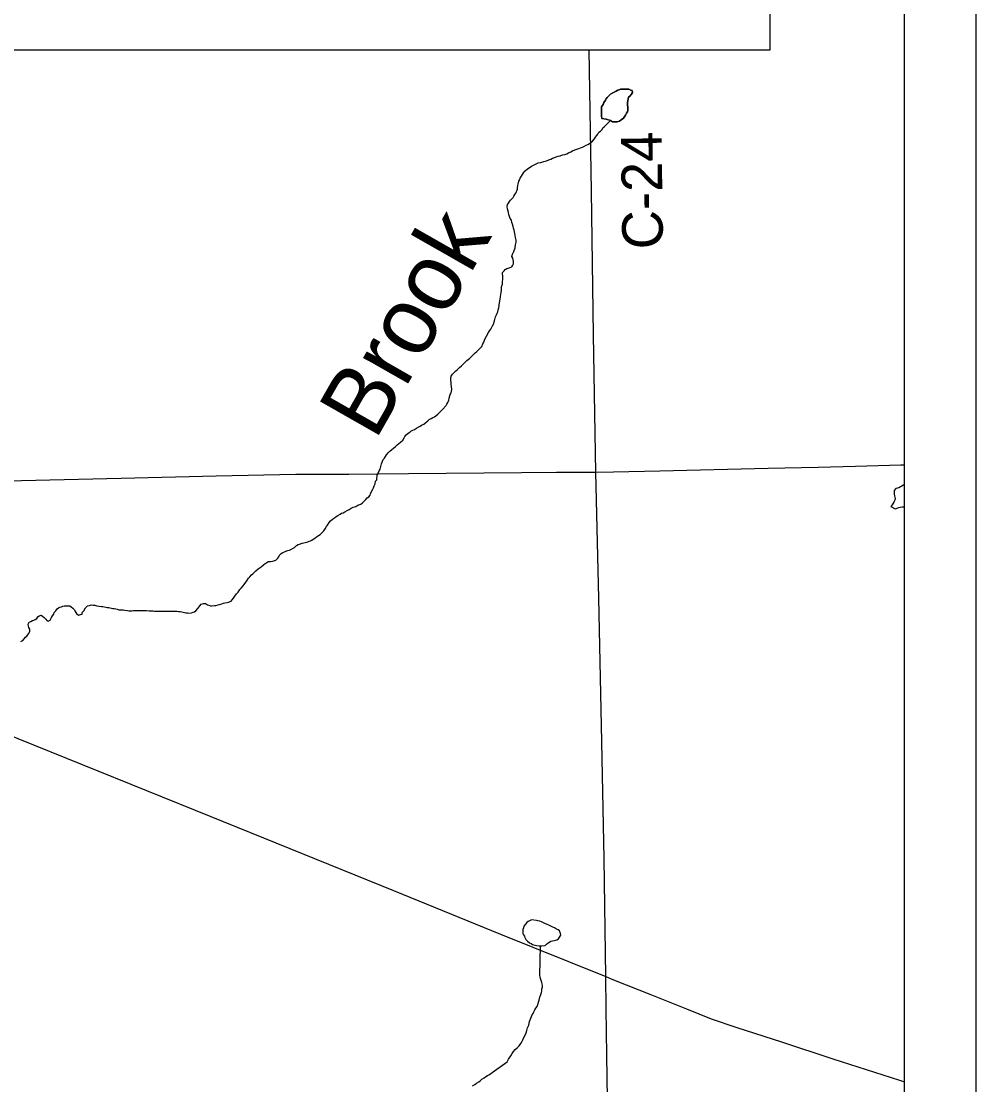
# Model space of a CAD drawing. Extents: x 0 to 34, y 0 to 22.
# Drawn here: x 7.926 to 9.262, y 16.207 to 17.696 of the extents above; entities that cross this region are included whole.
import ezdxf

# ---------------------------------------------------------------- set-up
doc = ezdxf.new("R2010")
doc.units = 0
for name, color, linetype in [('GM_X_County', 7, 'Continuous'), ('GM_X_County_Road', 7, 'Continuous'), ('GM_X_County_Road_Text', 7, 'Continuous'), ('GM_X_Minor_Lake', 7, 'Continuous'), ('GM_X_Minor_River', 7, 'Continuous'), ('GM_X_Minor_River_Text', 7, 'Continuous'), ('GM_X_Township', 7, 'Continuous'), ('GM_X_Township_Road', 7, 'Continuous'), ('GM_X_US_Route', 7, 'Continuous'), ('SH_Border', 7, 'Continuous'), ('SH_Data', 7, 'Continuous')]:
    doc.layers.add(name, color=color, linetype=linetype)

msp = doc.modelspace()

# ---------------------------------------------------------------- linework, layer by layer
at = {"layer": 'GM_X_County'}
msp.add_lwpolyline([(9.1622, 14.342), (9.1622, 21.1385), (2.3622, 21.1385), (2.3622, 14.3385), (9.0003, 14.3385)], dxfattribs=at)
at = {"layer": 'GM_X_County_Road'}
for points in [[(8.7438, 16.3585), (8.7415, 16.5238), (8.7381, 16.7101), (8.7342, 16.8882), (8.73, 17.0642), (8.7267, 17.2567), (8.7237, 17.4579), (8.7206, 17.6552)], [(8.7838, 14.3385), (8.7824, 14.3532), (8.7805, 14.4411), (8.7792, 14.5521), (8.7772, 14.6534), (8.7751, 14.7509), (8.773, 14.8406), (8.7698, 14.9457), (8.7683, 15.0013), (8.7648, 15.1439), (8.7597, 15.3395), (8.7581, 15.4244), (8.756, 15.5234), (8.7553, 15.5899), (8.7512, 15.8644), (8.748, 16.0625), (8.7455, 16.2486), (8.7445, 16.3137), (8.7438, 16.3585)]]:
    msp.add_lwpolyline(points, dxfattribs=at)
at = {"layer": 'GM_X_Minor_Lake'}
for points in [[(8.7789, 17.5993), (8.7762, 17.6004), (8.7739, 17.6007), (8.7712, 17.6007), (8.7694, 17.6007), (8.7671, 17.6007), (8.7644, 17.6003), (8.7625, 17.5995), (8.7606, 17.5991), (8.7584, 17.5976), (8.7557, 17.5964), (8.7538, 17.5953), (8.7504, 17.5933), (8.7482, 17.5911), (8.7459, 17.5888), (8.7444, 17.5868), (8.7433, 17.5849), (8.7414, 17.5819), (8.7403, 17.5792), (8.738, 17.5758), (8.7381, 17.5724), (8.7377, 17.5697), (8.7377, 17.567), (8.7381, 17.5632), (8.7382, 17.5594), (8.7445, 17.5584)], [(8.7445, 17.5584), (8.7382, 17.5594), (8.7381, 17.5632), (8.7377, 17.567), (8.7377, 17.5697), (8.7381, 17.5724), (8.738, 17.5758), (8.7403, 17.5792), (8.7414, 17.5819), (8.7433, 17.5849), (8.7444, 17.5868), (8.7459, 17.5888), (8.7482, 17.5911), (8.7504, 17.5933), (8.7538, 17.5953), (8.7557, 17.5964), (8.7584, 17.5976), (8.7606, 17.5991), (8.7625, 17.5995), (8.7644, 17.6003), (8.7671, 17.6007), (8.7694, 17.6007), (8.7712, 17.6007), (8.7739, 17.6007), (8.7762, 17.6004), (8.7789, 17.5993), (8.7808, 17.5985), (8.7812, 17.5959), (8.7797, 17.5936), (8.7774, 17.5905), (8.7755, 17.5894), (8.7751, 17.5871), (8.7748, 17.5844), (8.7744, 17.5817), (8.7744, 17.5798), (8.7745, 17.5779), (8.7749, 17.576), (8.7749, 17.5741), (8.7749, 17.5711), (8.7741, 17.5688), (8.773, 17.5669), (8.7715, 17.5642), (8.7685, 17.56), (8.7655, 17.5574), (8.7629, 17.5558), (8.7598, 17.5547), (8.7579, 17.5546), (8.7553, 17.5546), (8.7534, 17.555), (8.7507, 17.5565), (8.7445, 17.5584)], [(8.7445, 17.5584), (8.7507, 17.5565), (8.7534, 17.555), (8.7553, 17.5546), (8.7579, 17.5546), (8.7598, 17.5547), (8.7629, 17.5558), (8.7655, 17.5574), (8.7685, 17.56), (8.7715, 17.5642), (8.773, 17.5669), (8.7741, 17.5688), (8.7749, 17.5711), (8.7749, 17.5741), (8.7749, 17.576), (8.7745, 17.5779), (8.7744, 17.5798), (8.7744, 17.5817), (8.7748, 17.5844), (8.7751, 17.5871), (8.7755, 17.5894), (8.7774, 17.5905), (8.7797, 17.5936), (8.7812, 17.5959), (8.7808, 17.5985), (8.7789, 17.5993)], [(9.1622, 17.0473), (9.1622, 17.0473), (9.1603, 17.0461), (9.1584, 17.045), (9.1565, 17.0438), (9.1542, 17.0427), (9.1523, 17.0419), (9.1497, 17.0415), (9.1474, 17.0388), (9.1474, 17.0358), (9.1475, 17.0335), (9.1482, 17.0312), (9.149, 17.0278), (9.1487, 17.0255), (9.1475, 17.0236), (9.1449, 17.019), (9.1434, 17.0171), (9.1431, 17.0164)], [(9.1431, 17.0164), (9.1491, 17.013), (9.1518, 17.0141), (9.1541, 17.0149), (9.1559, 17.0157), (9.1586, 17.0161), (9.1613, 17.0161), (9.1622, 17.0161)], [(8.64, 16.4381), (8.6354, 16.4358), (8.6332, 16.4343), (8.6313, 16.432), (8.6294, 16.4293), (8.6287, 16.427), (8.6279, 16.4244), (8.628, 16.4203)], [(8.628, 16.4203), (8.628, 16.419), (8.6288, 16.4171), (8.6299, 16.4153), (8.6307, 16.4134), (8.6322, 16.4103), (8.6345, 16.4081), (8.6372, 16.4058), (8.6395, 16.4047), (8.6414, 16.4036), (8.6444, 16.4024), (8.6471, 16.4021), (8.6505, 16.4017), (8.6524, 16.4014), (8.6543, 16.4014), (8.6589, 16.4022), (8.6607, 16.4037), (8.6634, 16.4056), (8.6668, 16.4079), (8.6694, 16.4087), (8.6717, 16.4091), (8.6736, 16.4095), (8.6755, 16.4099), (8.6778, 16.4114), (8.6793, 16.4137), (8.6808, 16.4164), (8.6807, 16.419), (8.6792, 16.4225), (8.6773, 16.424), (8.675, 16.4251), (8.6723, 16.4266), (8.67, 16.4277), (8.6678, 16.4288), (8.6643, 16.4303), (8.6617, 16.4314), (8.6586, 16.4329), (8.656, 16.4341), (8.6537, 16.4352), (8.6518, 16.4359), (8.6487, 16.4367), (8.647, 16.4372)], [(8.647, 16.4372), (8.64, 16.4381)]]:
    msp.add_lwpolyline(points, dxfattribs=at)
at = {"layer": 'GM_X_Minor_River'}
for points in [[(8.6464, 17.4961), (8.6494, 17.4972), (8.6529, 17.498), (8.657, 17.4992), (8.6608, 17.5004), (8.6642, 17.5015), (8.6669, 17.5027), (8.6691, 17.5038), (8.6714, 17.5046), (8.6744, 17.5058), (8.6771, 17.5066), (8.6801, 17.5073), (8.6835, 17.5085), (8.6865, 17.5093), (8.6892, 17.5101), (8.6918, 17.5112), (8.6949, 17.5128), (8.6975, 17.5143), (8.7005, 17.5155), (8.7062, 17.5174), (8.7085, 17.5186), (8.7111, 17.5193), (8.713, 17.5201), (8.7164, 17.522), (8.7187, 17.5232), (8.721, 17.5247), (8.7229, 17.5259), (8.7251, 17.5278), (8.7281, 17.5309), (8.7293, 17.5332), (8.7311, 17.5351), (8.733, 17.5377), (8.7341, 17.5404), (8.7364, 17.5419), (8.7387, 17.5442), (8.7398, 17.5462), (8.7419, 17.5482)], [(8.7507, 17.5565), (8.7507, 17.5565), (8.7419, 17.5482)], [(8.5442, 17.2156), (8.5468, 17.2179), (8.5494, 17.2206), (8.5513, 17.2222), (8.5532, 17.2237), (8.5551, 17.2256), (8.557, 17.2275), (8.5592, 17.2298), (8.5611, 17.2317), (8.5634, 17.2333), (8.5653, 17.2352), (8.5702, 17.2405), (8.5717, 17.244), (8.5732, 17.2466), (8.5746, 17.2508), (8.5769, 17.255), (8.5795, 17.26), (8.5814, 17.2627), (8.5829, 17.2646), (8.5844, 17.2676), (8.5855, 17.2695), (8.587, 17.2726), (8.5877, 17.2749), (8.5885, 17.2783), (8.5896, 17.2821), (8.5911, 17.2848), (8.5918, 17.2871), (8.5926, 17.289), (8.5933, 17.2916), (8.5944, 17.2947), (8.5951, 17.3015), (8.5959, 17.3068), (8.5966, 17.3103), (8.5973, 17.316), (8.5977, 17.3194), (8.598, 17.324), (8.5991, 17.3274), (8.5995, 17.3293), (8.5998, 17.3358), (8.5998, 17.3377), (8.5998, 17.3395), (8.5994, 17.3414), (8.5994, 17.3441), (8.6016, 17.3464), (8.6031, 17.3483), (8.6054, 17.3495), (8.6073, 17.3499), (8.6099, 17.351), (8.6122, 17.3518), (8.6137, 17.3541), (8.6145, 17.356), (8.6148, 17.3594), (8.6144, 17.3617), (8.6136, 17.364), (8.6125, 17.3662), (8.6132, 17.3697), (8.6151, 17.3735), (8.6169, 17.3784), (8.6177, 17.3826), (8.6184, 17.3864), (8.6184, 17.3891), (8.6176, 17.3929), (8.6172, 17.3959), (8.6164, 17.3986), (8.6156, 17.4031), (8.6148, 17.4058), (8.6141, 17.4081), (8.6133, 17.4118), (8.6125, 17.4137), (8.6117, 17.4172), (8.6102, 17.4194), (8.6082, 17.4251), (8.6075, 17.4281), (8.6063, 17.4331), (8.6059, 17.4357), (8.6062, 17.4392), (8.6077, 17.4411), (8.6092, 17.4434), (8.6107, 17.4453), (8.6122, 17.4472), (8.6141, 17.4491), (8.6153, 17.451), (8.6164, 17.4529), (8.6179, 17.4552), (8.6201, 17.4605), (8.6205, 17.4624), (8.6208, 17.4659), (8.6212, 17.4678), (8.6223, 17.4716), (8.6234, 17.4739), (8.6242, 17.4758), (8.6257, 17.4788), (8.6272, 17.4811), (8.6287, 17.4834), (8.6309, 17.4861), (8.6343, 17.4888), (8.6381, 17.4914), (8.64, 17.4926), (8.6419, 17.4938), (8.6445, 17.4949), (8.6464, 17.4961)], [(8.3342, 16.9709), (8.3365, 16.9721), (8.3388, 16.974), (8.3418, 16.9759), (8.3441, 16.9771), (8.3463, 16.9797), (8.3493, 16.9824), (8.3512, 16.9851), (8.3531, 16.9885), (8.3542, 16.9904), (8.3565, 16.9939), (8.3587, 16.9966), (8.3614, 16.9985), (8.364, 17.0004), (8.3666, 17.0023), (8.3689, 17.0039), (8.3719, 17.0058), (8.3738, 17.0069), (8.3761, 17.0077), (8.3787, 17.0089), (8.3821, 17.0108), (8.3848, 17.0123), (8.3874, 17.0139), (8.3905, 17.0154), (8.3939, 17.0166), (8.3969, 17.0181), (8.4011, 17.0197), (8.4033, 17.0216), (8.4052, 17.0235), (8.4078, 17.0262), (8.4101, 17.0285), (8.4124, 17.03), (8.4139, 17.0323), (8.4146, 17.0342), (8.4157, 17.0365), (8.4176, 17.0407), (8.4187, 17.0426), (8.4198, 17.0456), (8.4209, 17.0483), (8.4217, 17.0517), (8.4232, 17.054), (8.4239, 17.0601), (8.4269, 17.0666), (8.428, 17.0685), (8.4298, 17.0761), (8.4325, 17.0822), (8.4343, 17.0841), (8.4355, 17.0864), (8.437, 17.0887), (8.4392, 17.0914), (8.4415, 17.0937), (8.4445, 17.096), (8.4468, 17.0979), (8.4494, 17.1006), (8.4517, 17.1029), (8.4543, 17.1048), (8.4566, 17.1067), (8.4596, 17.1094), (8.4615, 17.1124), (8.4626, 17.1144), (8.4645, 17.1166), (8.4675, 17.1193), (8.4694, 17.1205), (8.4712, 17.122), (8.4739, 17.1232), (8.4762, 17.1243), (8.4788, 17.1259), (8.4822, 17.1278), (8.4841, 17.1289), (8.486, 17.1301), (8.489, 17.1316), (8.4924, 17.1343), (8.4947, 17.1362), (8.4969, 17.1382), (8.4996, 17.1397), (8.5018, 17.1409), (8.5041, 17.142), (8.506, 17.1435), (8.5086, 17.1455), (8.5105, 17.1474), (8.5128, 17.1497), (8.5154, 17.1524), (8.5207, 17.1577), (8.5214, 17.1596), (8.5226, 17.1619), (8.5241, 17.1653), (8.5248, 17.168), (8.5259, 17.173), (8.5274, 17.1756), (8.5278, 17.1775), (8.5285, 17.1806), (8.5277, 17.1878), (8.5269, 17.1958), (8.5276, 17.1988), (8.5295, 17.2015), (8.5317, 17.2038), (8.5336, 17.2057), (8.5359, 17.2076), (8.5393, 17.2111), (8.5419, 17.2134), (8.5442, 17.2156)], [(8.0895, 16.8707), (8.0929, 16.8707), (8.0951, 16.8708), (8.0982, 16.8708), (8.1008, 16.8708), (8.1046, 16.8704), (8.1073, 16.8705), (8.1103, 16.8705), (8.1122, 16.8701), (8.1145, 16.8701), (8.1172, 16.8698), (8.1202, 16.8698), (8.1225, 16.8698), (8.1248, 16.8698), (8.1267, 16.8698), (8.1301, 16.8699), (8.132, 16.8699), (8.1339, 16.8699), (8.1361, 16.8699), (8.1384, 16.8699), (8.1407, 16.8699), (8.1437, 16.87), (8.1456, 16.8696), (8.1483, 16.8696), (8.1506, 16.8689), (8.154, 16.8681), (8.1559, 16.8678), (8.1582, 16.8674), (8.1601, 16.867), (8.1639, 16.8675), (8.1665, 16.8686), (8.1684, 16.869), (8.1703, 16.8705), (8.1729, 16.8736), (8.1759, 16.8774), (8.1774, 16.8797), (8.1808, 16.8805), (8.1835, 16.8805), (8.1865, 16.879), (8.1884, 16.8783), (8.1907, 16.8775), (8.1926, 16.8775), (8.196, 16.8779), (8.1979, 16.878), (8.2013, 16.8787), (8.2032, 16.8795), (8.2063, 16.8803), (8.2089, 16.8811), (8.2108, 16.8815), (8.2138, 16.8823), (8.2157, 16.8827), (8.2195, 16.8838), (8.2207, 16.8857), (8.2229, 16.888), (8.2248, 16.8911), (8.227, 16.8941), (8.2293, 16.8964), (8.2315, 16.9002), (8.2334, 16.9022), (8.2361, 16.9056), (8.2379, 16.9075), (8.2413, 16.9125), (8.2436, 16.9163), (8.2458, 16.9182), (8.2481, 16.9209), (8.25, 16.9224), (8.2519, 16.9243), (8.2541, 16.9263), (8.2575, 16.9293), (8.2613, 16.932), (8.2647, 16.9347), (8.2669, 16.9366), (8.2688, 16.9378), (8.2715, 16.9393), (8.2745, 16.9397), (8.2775, 16.9401), (8.2794, 16.9405), (8.2821, 16.9413), (8.2847, 16.9443), (8.2862, 16.9462), (8.2874, 16.9482), (8.2896, 16.9508), (8.2919, 16.952), (8.2941, 16.9531), (8.296, 16.9539), (8.2987, 16.9547), (8.301, 16.9555), (8.3029, 16.9562), (8.3063, 16.9582), (8.3081, 16.9593), (8.3112, 16.962), (8.3134, 16.9635), (8.3153, 16.9639), (8.3191, 16.9651), (8.3214, 16.9655), (8.3248, 16.9667), (8.3267, 16.9671), (8.3286, 16.9678), (8.3305, 16.9682), (8.3324, 16.9694), (8.3342, 16.9709)], [(7.9251, 16.8273), (7.9281, 16.8289), (7.9315, 16.8335), (7.9334, 16.835), (7.936, 16.8384), (7.9375, 16.8415), (7.9375, 16.8449), (7.9363, 16.8472), (7.9359, 16.8491), (7.9355, 16.8517), (7.937, 16.8548), (7.9389, 16.8555), (7.9415, 16.8567), (7.9434, 16.8575), (7.9453, 16.8583), (7.9476, 16.8598), (7.9491, 16.8621), (7.951, 16.8636), (7.9536, 16.8644), (7.9555, 16.8629), (7.9578, 16.861), (7.9601, 16.8587), (7.9613, 16.8569), (7.9636, 16.8561), (7.9662, 16.8576), (7.9681, 16.8611), (7.9696, 16.8634), (7.9711, 16.8657), (7.9718, 16.8683), (7.9741, 16.8706), (7.976, 16.8733), (7.9778, 16.8748), (7.9797, 16.8756), (7.982, 16.876), (7.9839, 16.8768), (7.9858, 16.8772), (7.9907, 16.8772), (7.9938, 16.8772), (7.9957, 16.8761), (7.998, 16.8742), (8.0003, 16.8716), (8.001, 16.8693), (8.003, 16.8667), (8.0056, 16.8644), (8.0087, 16.8652), (8.0109, 16.8656), (8.0109, 16.8679), (8.0132, 16.8702), (8.0154, 16.8747), (8.0184, 16.8774), (8.0211, 16.8778), (8.0234, 16.8786), (8.0264, 16.8782), (8.0287, 16.8782), (8.0313, 16.8775), (8.0348, 16.8768), (8.0382, 16.8764), (8.0401, 16.8764), (8.0439, 16.8757), (8.0458, 16.8753), (8.0484, 16.875), (8.0519, 16.8742), (8.0538, 16.8739), (8.0557, 16.8735), (8.0579, 16.8731), (8.0598, 16.8728), (8.0625, 16.872), (8.0652, 16.8717), (8.0682, 16.8717), (8.0709, 16.8713), (8.0743, 16.871), (8.0762, 16.8706), (8.0781, 16.8706), (8.0803, 16.8706), (8.083, 16.8707), (8.0864, 16.8707), (8.0895, 16.8707)], [(8.6059, 16.2391), (8.6077, 16.243), (8.6111, 16.2475), (8.6129, 16.251), (8.6148, 16.2536), (8.6171, 16.2563), (8.6197, 16.259), (8.6227, 16.2617), (8.625, 16.2651), (8.6268, 16.2682), (8.6276, 16.2701), (8.6295, 16.2743), (8.6313, 16.2777), (8.6325, 16.2796), (8.6336, 16.283), (8.6343, 16.2868), (8.6354, 16.2888), (8.6362, 16.2907), (8.6373, 16.2956), (8.641, 16.3051), (8.6421, 16.307), (8.6432, 16.3093), (8.6444, 16.312), (8.6459, 16.3143), (8.6477, 16.3166), (8.6488, 16.3196), (8.6496, 16.3227), (8.6507, 16.3257), (8.6518, 16.3299), (8.6529, 16.3333), (8.6537, 16.3364), (8.6544, 16.3383), (8.6544, 16.3413), (8.6551, 16.3436), (8.6551, 16.3455), (8.6547, 16.3486), (8.6543, 16.3505), (8.6535, 16.3531), (8.6524, 16.3558), (8.652, 16.358), (8.6516, 16.3599), (8.6524, 16.4014)], [(8.5575, 16.2056), (8.5605, 16.2076), (8.5631, 16.2095), (8.5661, 16.2111), (8.5684, 16.2131), (8.5706, 16.215), (8.5736, 16.217), (8.5762, 16.2186), (8.5785, 16.2202), (8.5804, 16.221), (8.5826, 16.2225), (8.5849, 16.2241), (8.6059, 16.2391)]]:
    msp.add_lwpolyline(points, dxfattribs=at)
at = {"layer": 'GM_X_Township'}
msp.add_line((9.1622, 14.342), (9.1622, 19.7691), dxfattribs=at)
at = {"layer": 'GM_X_Township_Road'}
for points in [[(9.1622, 17.0743), (9.1569, 17.0742), (9.0934, 17.0725), (9.0414, 17.0712), (8.9713, 17.0695), (8.8196, 17.0659), (8.7549, 17.0644), (8.73, 17.0642)], [(8.73, 17.0642), (8.6747, 17.0639), (8.6261, 17.0637), (8.4676, 17.0622), (8.3844, 17.0614), (8.3099, 17.0612), (8.1987, 17.0591), (8.0654, 17.0556), (7.926, 17.0523), (7.8621, 17.0506), (7.7682, 17.0478), (7.7227, 17.0471)]]:
    msp.add_lwpolyline(points, dxfattribs=at)
at = {"layer": 'GM_X_US_Route'}
for points in [[(7.7905, 16.7451), (7.921, 16.6919), (8.1911, 16.5828), (8.4468, 16.4792), (8.5967, 16.4181), (8.642, 16.3998)], [(8.642, 16.3998), (8.7438, 16.3585), (8.7549, 16.3542), (8.8079, 16.333), (8.8569, 16.3133), (8.8912, 16.2994), (8.9275, 16.2871), (8.9899, 16.2671), (9.0616, 16.2436), (9.1552, 16.2134), (9.1622, 16.2111)]]:
    msp.add_lwpolyline(points, dxfattribs=at)
at = {"layer": 'SH_Border'}
msp.add_lwpolyline([(6.9977, 18.4031), (8.9734, 18.4031), (8.9734, 17.6552), (6.9977, 17.6552)], close=True, dxfattribs=at)
at = {"layer": 'SH_Data'}
msp.add_line((9.2617, 21.2383), (9.2617, 14.2383), dxfattribs=at)

# ---------------------------------------------------------------- texts
at = {"layer": 'GM_X_County_Road_Text'}
msp.add_text('C-24', height=0.05682, rotation=90.6858, dxfattribs=at).set_placement((8.824, 17.3767))
at = {"layer": 'GM_X_Minor_River_Text'}
msp.add_text('Brook', height=0.09476, rotation=60.3298, dxfattribs=at).set_placement((8.4212, 17.1075))

doc.saveas('drawing.dxf')
